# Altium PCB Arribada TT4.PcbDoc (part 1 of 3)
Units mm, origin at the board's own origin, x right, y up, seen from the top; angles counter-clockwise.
Board outline 56 x 35 mm, 6 copper layers (Top Layer, L2GND, L3, L4, L5GND, Bottom Layer), stack 0.865 mm thick; 99 components, 88 nets, 417 pads, 769 vias.
Unrouted connection lines stored in the file: 31.
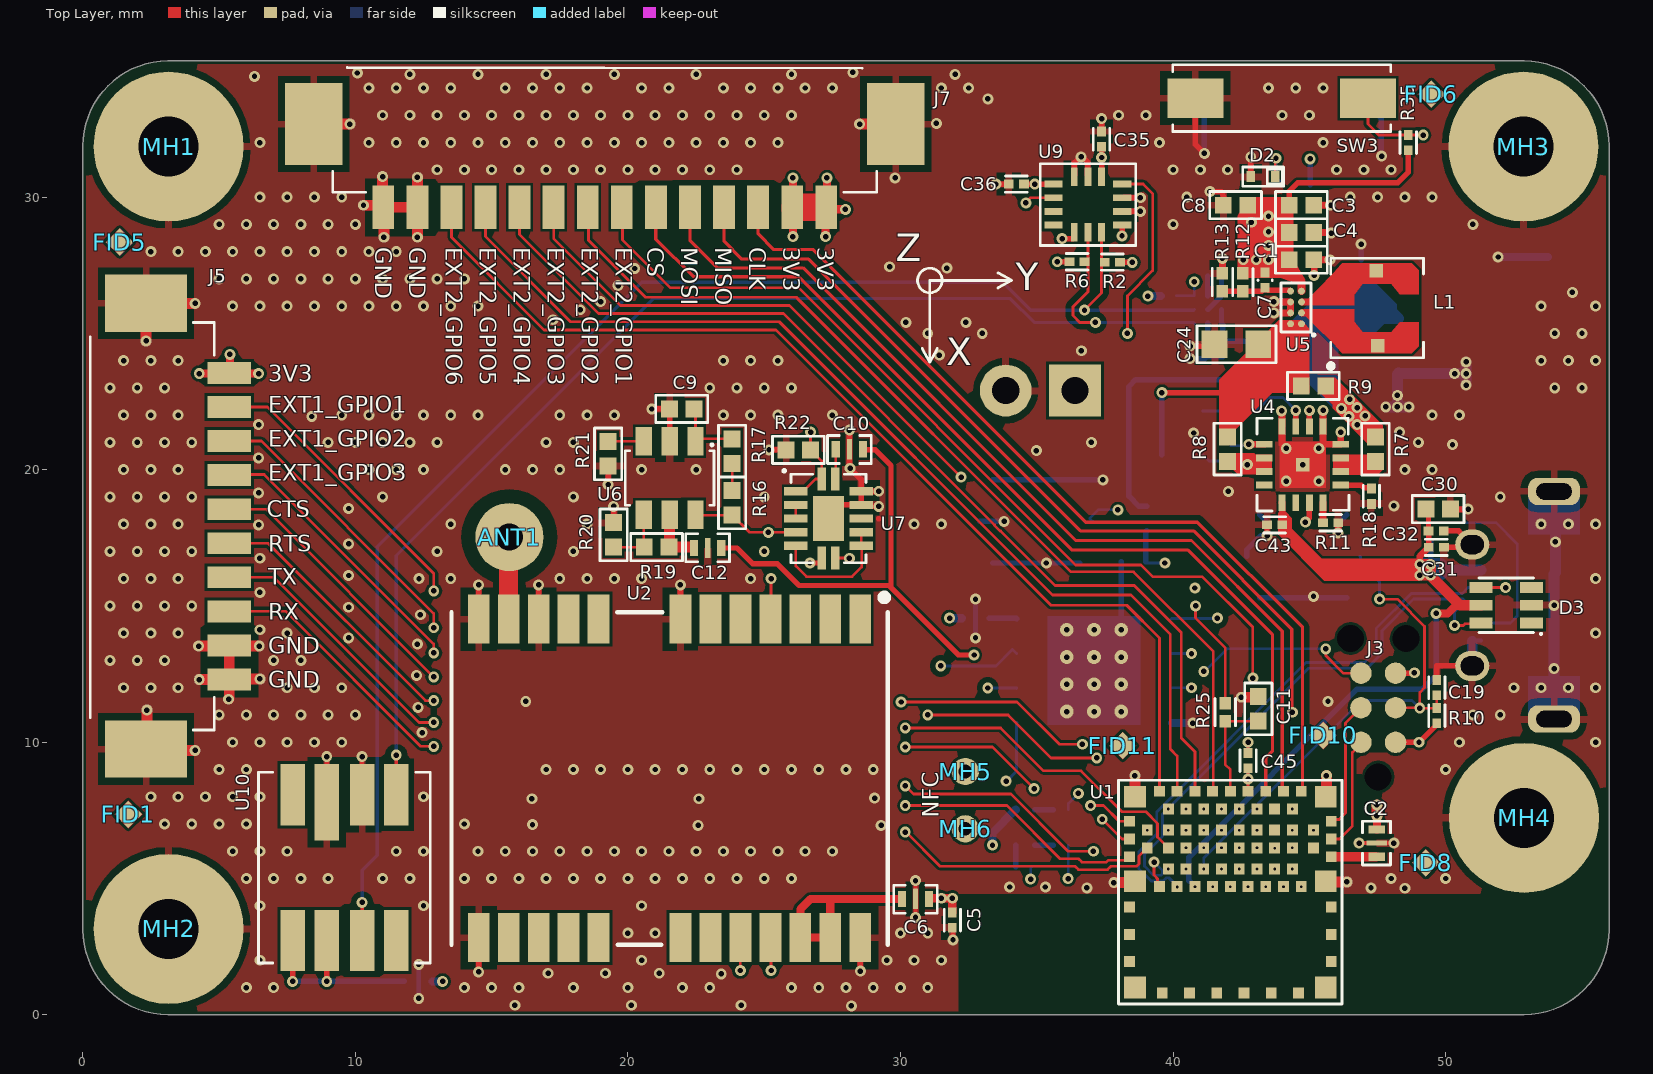
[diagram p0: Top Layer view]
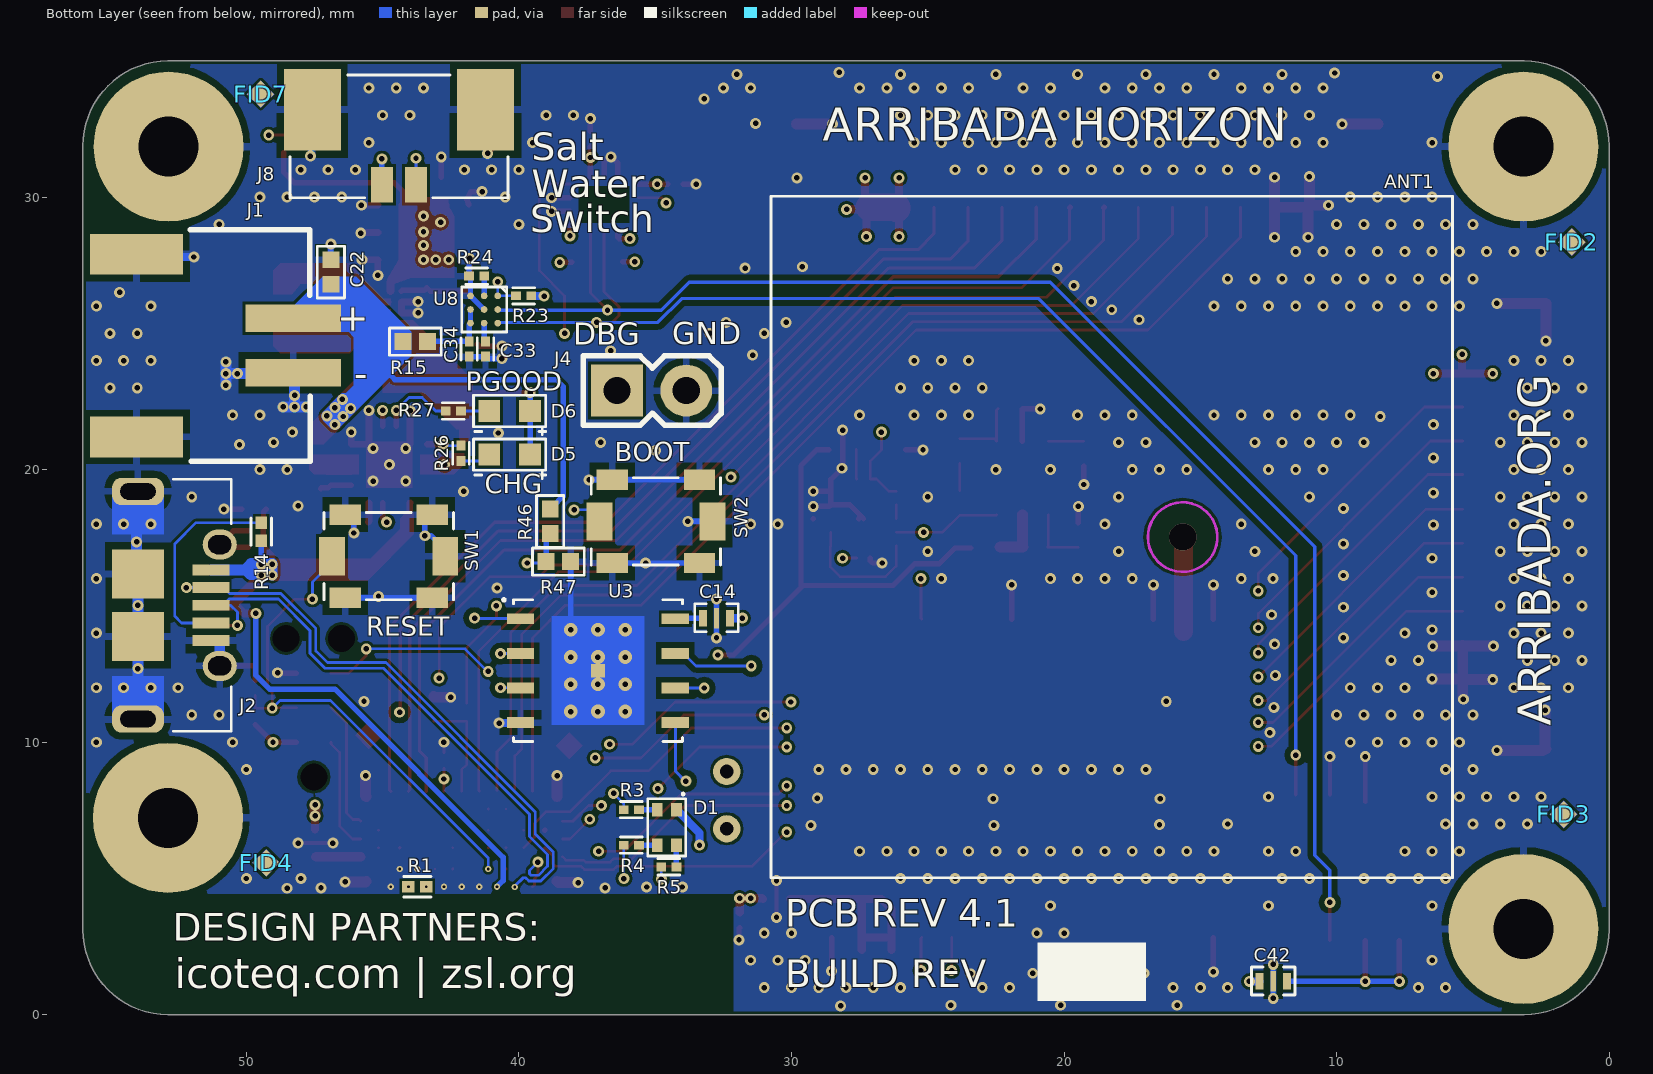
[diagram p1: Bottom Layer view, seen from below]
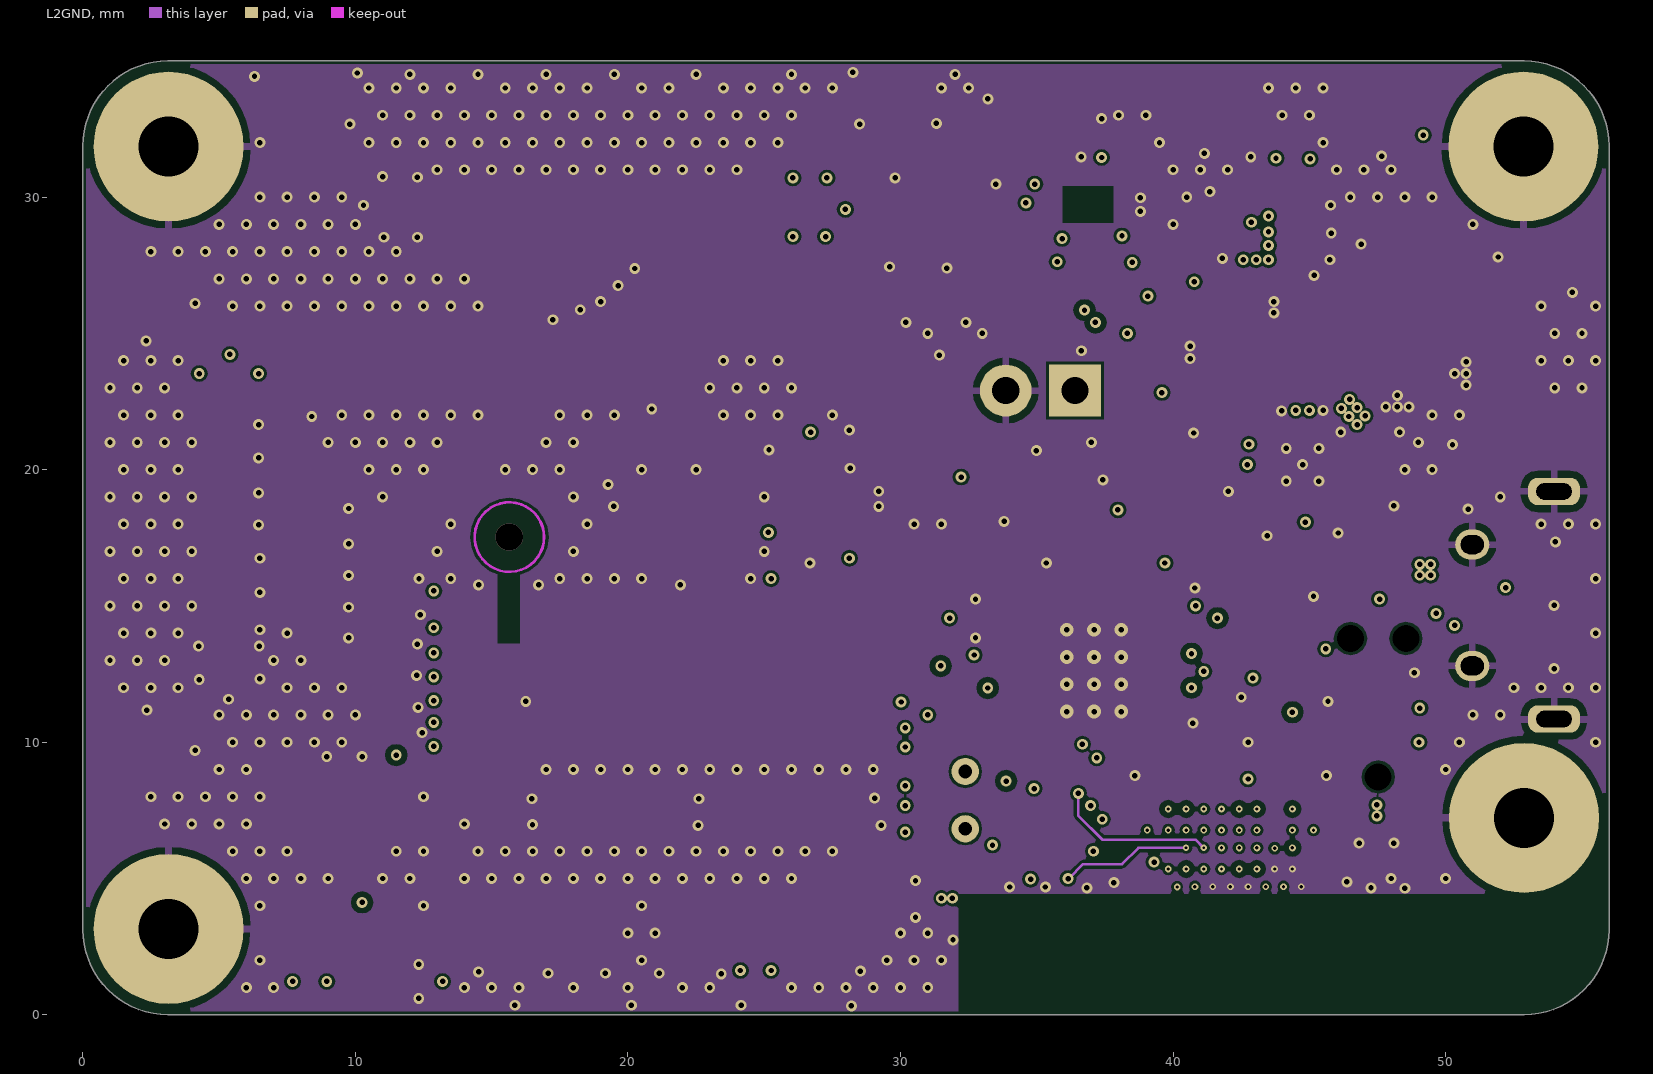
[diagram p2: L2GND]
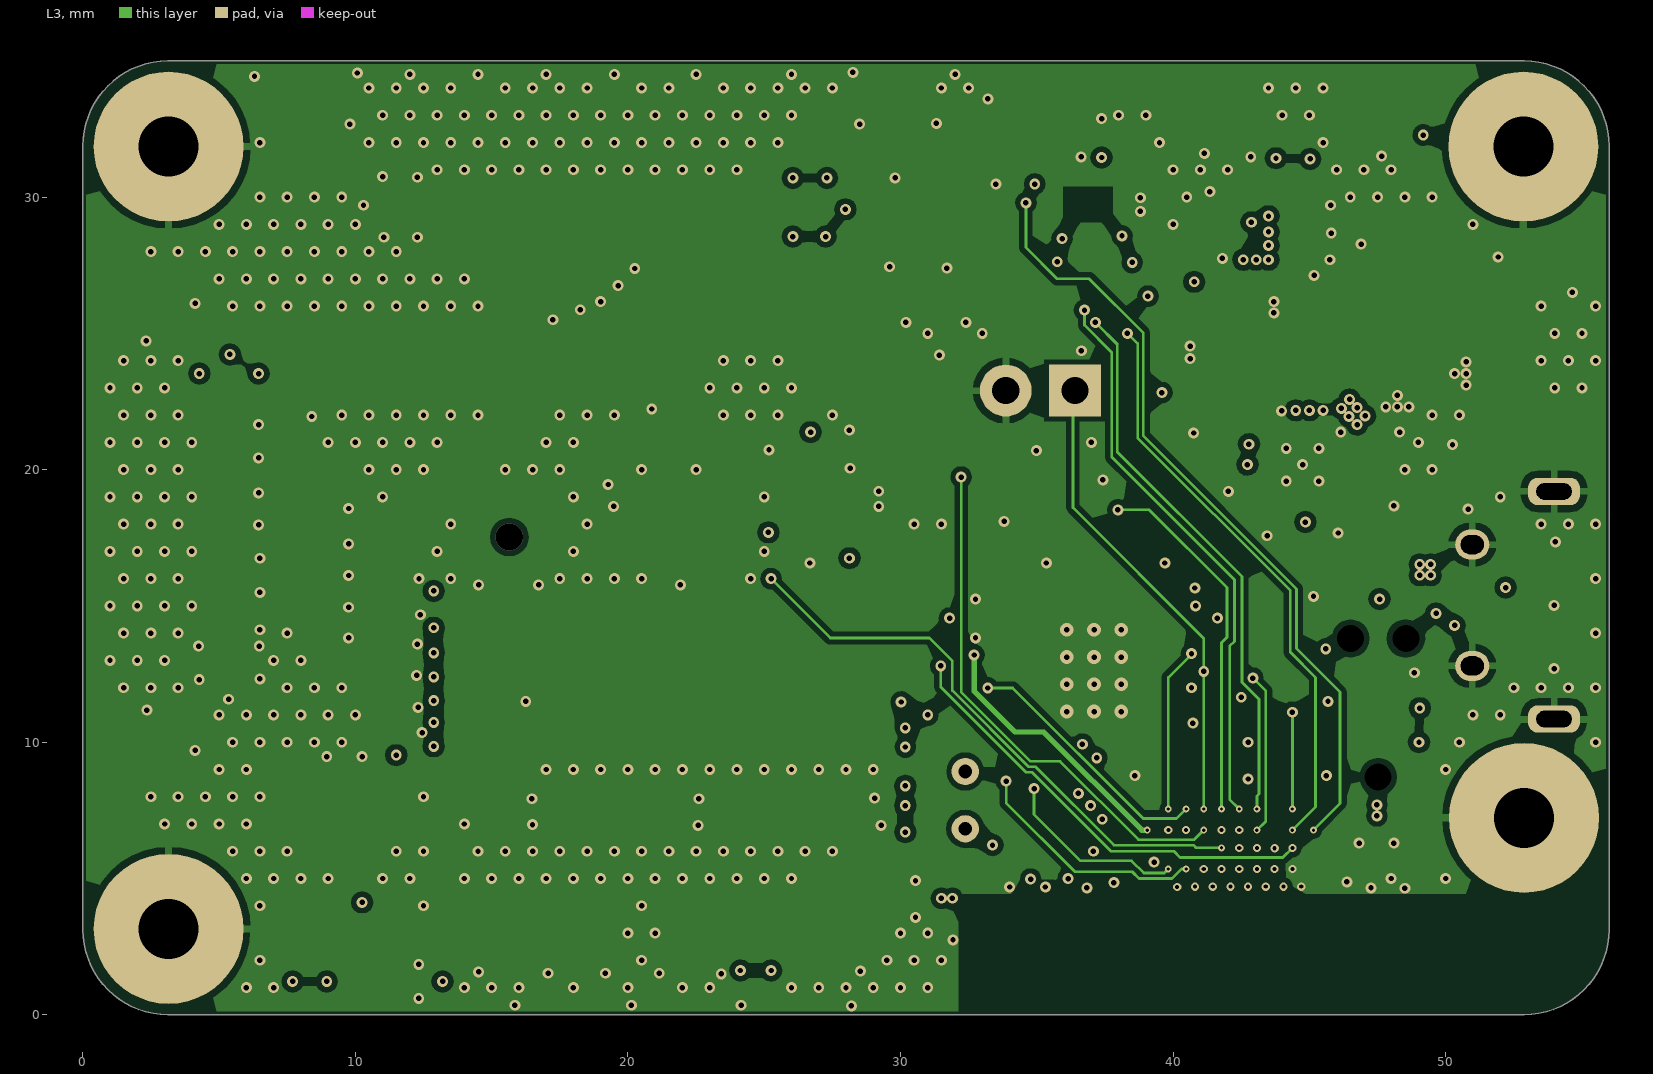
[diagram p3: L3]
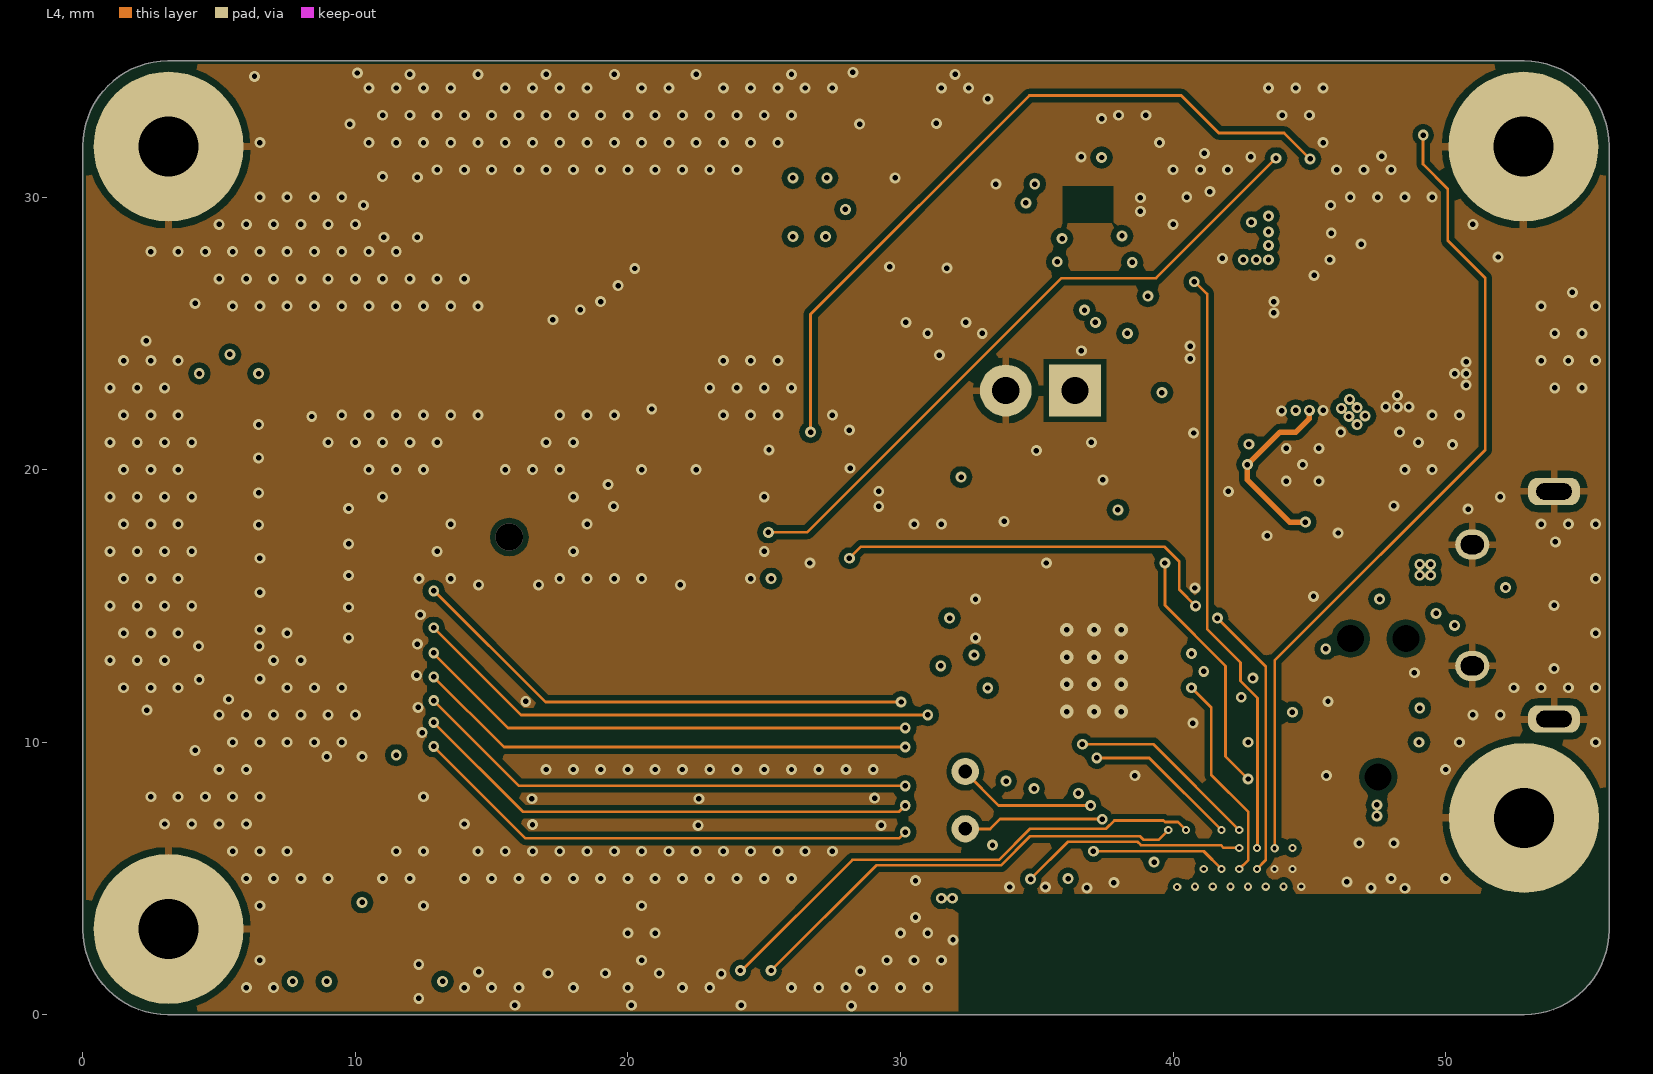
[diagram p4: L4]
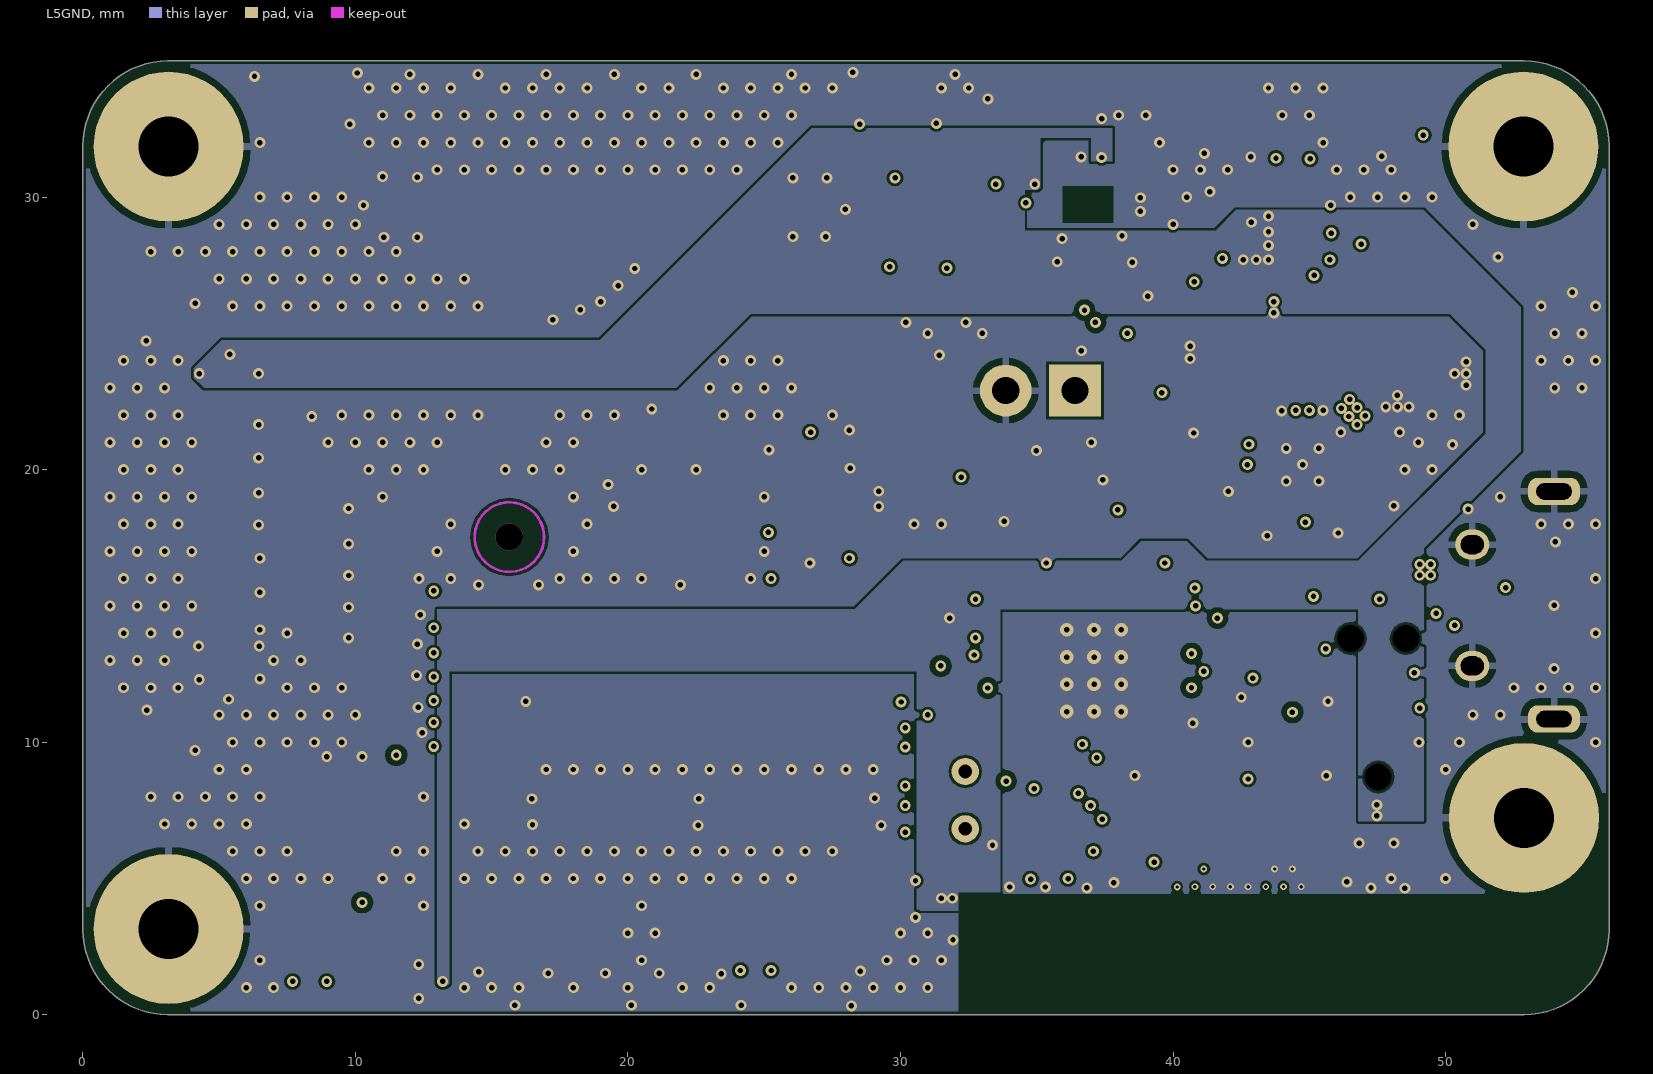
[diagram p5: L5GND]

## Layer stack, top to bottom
Top Solder: solder mask 0.02, Solder Resist, Dk 4.1
Top Layer: signal copper 0.012
Dielectric1: prepreg 0.086, EM-827B-1080_RC68, Dk 3.8
L2GND: signal copper 0.012
Dielectric2: prepreg 0.064, EM-827B-106RC76, Dk 3.7
Dielectric3: core 0.064, EM-827B-106RC76, Dk 3.7
L3: signal copper 0.017
Dielectric4: core 0.355, EM827B, Dk 4.4
L4: signal copper 0.017
Dielectric5: prepreg 0.064, EM-827B-106RC76, Dk 3.7
Dielectric6: dielectric 0.064, EM-827B-106RC76, Dk 3.7
L5GND: signal copper 0.012
Dielectric7: prepreg 0.086, EM-827B-1080_RC68, Dk 3.8
Bottom Layer: signal copper 0.012
Bottom Solder: solder mask 0.02, Solder Resist, Dk 4.1

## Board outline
3.125,0 cw(c3.15,3.15) 0,3.125 0,31.875 cw(c3.15,31.85) 3.125,35 3.15,35 52.875,35 cw(c52.85,31.85) 56,31.875 56,3.125 cw(c52.85,3.15) 52.875,0

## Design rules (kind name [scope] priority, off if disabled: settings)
Clearance "Antenna Pin Top" [InComponent('ANT1')AND OnLayer('Top Layer')] p1: gap=0.5 ignorepadtopadclearanceinfootprint=FALSE
Clearance "50R Clearance" [InNetClass('50R_track') vs InPolygon] p2: gap=0.2 ignorepadtopadclearanceinfootprint=FALSE except(0: Arc-Hole Track-Hole SMDPad-Hole THPad-Hole Via-Hole Fill-Hole Poly-Hole Region-Hole Text-Hole)
Clearance Polygon_named [All vs InNamedPolygon('TOP_GND')or InNamedPolygon('L2GND')or InNamedPolygon('L3_GND')or InNamedPolygon('L4_GND')or InNamedPolygon('L5GND')or InNamedPolygon('BOT_GND')] p3: gap=0.2 ignorepadtopadclearanceinfootprint=FALSE except(0: Arc-Hole Track-Hole SMDPad-Hole THPad-Hole Via-Hole Fill-Hole Poly-Hole Region-Hole Text-Hole)
Clearance [All] p4: gap=0.1 ignorepadtopadclearanceinfootprint=FALSE except(0: Arc-Hole Track-Hole SMDPad-Hole THPad-Hole Via-Hole Fill-Hole Poly-Hole Region-Hole Text-Hole)
Clearance Polygon_general [All vs InPolygon] p5: gap=0.2 ignorepadtopadclearanceinfootprint=FALSE except(0: Arc-Hole Track-Hole SMDPad-Hole THPad-Hole Via-Hole Fill-Hole Poly-Hole Region-Hole Text-Hole)
ComponentClearance [All] p1 off: gap=0.254 collisioncheckmode=3 verticalgap=0.254 showdistances=FALSE
DiffPairsRouting [All] p1: maxlimit=0.108 minlimit=0.102 mostfreqgap=0.108 toplayer_mingap=0.108 toplayer_minwidth=0.1 toplayer_maxwidth=0.102 toplayer_prefwidth=0.102 midlayer1_mingap=0.108 midlayer1_minwidth=0.1 midlayer1_maxwidth=0.102 midlayer1_prefwidth=0.102 midlayer2_maxgap=0.102 midlayer2_prefgap=0.102 midlayer2_minwidth=0.152 midlayer2_maxwidth=0.152 midlayer2_prefwidth=0.152 midlayer3_maxgap=0.102 midlayer3_prefgap=0.102 midlayer3_minwidth=0.152 midlayer3_maxwidth=0.152 midlayer3_prefwidth=0.152 midlayer4_mingap=0.108 midlayer4_minwidth=0.1 midlayer4_maxwidth=0.102 midlayer4_prefwidth=0.102 bottomlayer_mingap=0.108 bottomlayer_minwidth=0.1 bottomlayer_maxwidth=0.102 bottomlayer_prefwidth=0.102 maxuncoupledlength=12.7
FabricationTestPointUsage TestPointUsage [All] p1: valid=0 allowmultiple=FALSE
FabricationTestPointUsage [All] p2: valid=0 allowmultiple=FALSE
FabricationTestpoint Testpoint [All] p1: side=3 testpointundercomponent=TRUE minsize=1.016 maxsize=2.54 preferedsize=1.524 minholesize=0 maxholesize=1.016 preferedholesize=0.813 testpointgrid=0.025 allowsidetop=TRUE allowsidebottom=TRUE usegrid=TRUE gridtolerance=0
FabricationTestpoint [All] p2: side=3 testpointundercomponent=TRUE minsize=1.016 maxsize=2.54 preferedsize=1.524 minholesize=0 maxholesize=1.016 preferedholesize=0.813 testpointgrid=0.025 allowsidetop=TRUE allowsidebottom=TRUE usegrid=TRUE gridtolerance=0
Height [All] p1 off: minheight=0 maxheight=25.4 prefheight=12.7
HoleSize [All] p1: absolutevalues=TRUE maxlimit=6 minlimit=0.015 maxpercent=80.000 minpercent=20.000
HoleSize HoleSize_1 [All] p2: absolutevalues=TRUE maxlimit=2.54 minlimit=0.025 maxpercent=80.000 minpercent=20.000
HoleSize HoleSize_2 [All] p3: absolutevalues=TRUE maxlimit=5 minlimit=0.25 maxpercent=80.000 minpercent=20.000
HoleToHoleClearance [All] p1: gap=0.2 allowstackedmicrovias=TRUE
MinimumAnnularRing [All] p1: minimumring=0.062
MinimumSolderMaskSliver [All] p1 off: minsoldermaskwidth=0.1
PlaneClearance [All] p1: clearance=0.12
PlaneConnect [All] p1: planeconnectstyle=Direct reliefexpansion=0.508 reliefentries=4 reliefconductorwidth=0.254 reliefairgap=0.254
PolygonConnect PolygonConnect_GND [All vs IsNamedPolygon('TJ_GND')] p1: connectstyle=Direct reliefconductorwidth=0.254 reliefentries=4 polygonreliefangle="90 Angle" airgapwidth=0.254
PolygonConnect "PolygonToVia Connect" [IsVia] p2: connectstyle=Direct reliefconductorwidth=0.254 reliefentries=4 polygonreliefangle="90 Angle" airgapwidth=0.254
PolygonConnect PolygonConnect_1 [All] p3: connectstyle=Relief reliefconductorwidth=0.254 reliefentries=4 polygonreliefangle="90 Angle" airgapwidth=0.254
RoutingVias "Thru via" [InDrillLayerPair('Top Layer - Bottom Layer')] p1: holewidth=0.2 width=0.4 viastyle="Through Hole" minholewidth=0.15 minwidth=0.3 maxholewidth=0.2 maxwidth=0.4
RoutingVias TopMicrovia [InDrillLayerPair('Top Layer - L2GND')] p2: holewidth=0.1 width=0.23 viastyle="Through Hole" minholewidth=0.1 minwidth=0.23 maxholewidth=0.15 maxwidth=0.3
RoutingVias BotMicrovia [InDrillLayerPair('L5GND - Bottom Layer')] p3: holewidth=0.1 width=0.23 viastyle="Through Hole" minholewidth=0.1 minwidth=0.23 maxholewidth=0.15 maxwidth=0.3
RoutingVias L2-3Microvia [InDrillLayerPair('L2GND - L3')] p4: holewidth=0.125 width=0.25 viastyle="Through Hole" minholewidth=0.125 minwidth=0.25 maxholewidth=0.2 maxwidth=0.4
RoutingVias L4-5Microvia [InDrillLayerPair('L4 - L5GND')] p5: holewidth=0.125 width=0.25 viastyle="Through Hole" minholewidth=0.125 minwidth=0.25 maxholewidth=0.2 maxwidth=0.4
RoutingVias BuriedviaL3-4 [InDrillLayerPair('L3 - L4')] p6: holewidth=0.15 width=0.3 viastyle="Through Hole" minholewidth=0.15 minwidth=0.3 maxholewidth=0.15 maxwidth=0.3
SilkToSilkClearance [All] p1: silktosilkclearance=0.001
SilkToSolderMaskClearance SilkscreenOverComponentPads [IsPad] p1: minsilkscreentomaskgap=0.001 clearancetoexposedcopper=TRUE
SilkToSolderMaskClearance [IsPad] p2: minsilkscreentomaskgap=0.051 clearancetoexposedcopper=FALSE
SolderMaskExpansion [All] p1: expansion=0.05
Width Width_50R [InNetClass('50R_track')] p1: maxlimit=0.127 minlimit=0.1 preferedwidth=0.102 toplayer_maxwidth=0.121 toplayer_prefwidth=0.121 bottomlayer_maxwidth=0.121 bottomlayer_prefwidth=0.121 minimp=50.000000 maximp=50.000000 favimp=50.000000
Width [All] p2: maxlimit=5 minlimit=0.1 preferedwidth=0.1 minimp=50.000000 maximp=50.000000 favimp=50.000000
18 further rules are at their usual default settings.

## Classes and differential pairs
net class 50R_track: NetANT1_1 NetJ7_3 NetJ7_4 NetJ7_5 NetJ7_6 NetR2_1 NetR6_1 NetU1_11 NetU1_17 NetU1_19 NetU1_45 NetU1_47 NetU1_57 NetU4_C8
component class "Sensors and Interfaces": C9 C10 C11 C12 C35 C36 C42 D2 J3 J4 J5 J7 J8 R16 R17 R19 R20 R21 R22 R25 R35 SW3 U6 U7 U9 U10
component class Power: C1 C3 C4 C7 C8 C22 C24 C30 C31 C32 C33 C34 C43 C? D3 D5 D6 D? FID1 FID2 FID3 FID4 FID5 FID6 FID7 FID8 FID10 FID11 J1 J2 J? L1 L? MH1 MH2 MH3 MH4 Q? R7 R8 R9 R11 R12 R13 R14 R15 R18 R23 R24 R26 R27 R? U4 U5 U8 U?
component class MCU: C2 C14 C19 C45 D1 MH5 MH6 R1 R2 R3 R4 R5 R6 R10 R46 R47 SW1 SW2 U1 U3
component class GNSS: ANT1 C5 C6 U2
differential pair USB_D: +USB_D_P -USB_D_N

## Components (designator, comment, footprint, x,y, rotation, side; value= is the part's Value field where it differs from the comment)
ANT1 "2JCP2540101Ga" 2JCP2540101GA 18.25,17.525 r270 bottom locked
C1 "10UF 0402 6.3V 20% X5R" CAP0402N 44.709,27.7 r180 top value=10uF
C2 "470NF 0402 6.3V +50%/-20%" YFF15PC 47.475,6.3 r270 top value=470nF
C3 "10UF 0402 6.3V 20% X5R" CAP0402N 44.709,29.7 r180 top value=10uF
C4 "10UF 0402 6.3V 20% X5R" CAP0402N 44.709,28.7 r180 top value=10uF
C5 "1UF 0201 10V 20% X5R" CAP0201L 31.9,3.475 r90 top value=1uF
C6 "470NF 0402 6.3V +50%/-20%" YFF15PC 30.55,4.25 r0 top value=470nF
C7 "CAP CER 10PF 0201 25V 5% C0G" Passive0201L 43.375,26.95 r90 top value=10pF
C8 "CAP NF 0402" CAP0402N_NF 42.29,29.7 r0 top value=NF
C9 "10NF 0402 16V 20% X7R" CAP0402N 21.975,22.23 r0 top value=10nF
C10 "470NF 0402 6.3V +50%/-20%" YFF15PC 28.125,20.75 r0 top value=470nF
C11 "1NF 0402 50V 5%" CAP0402N 43.125,11.225 r270 top value=1nF
C12 "470NF 0402 6.3V +50%/-20%" YFF15PC 22.925,17.125 r180 top value=470nF
C14 "470NF 0402 6.3V +50%/-20%" YFF15PC 32.75,14.55 r0 bottom value=470nF
C19 "100NF 0201 35V 10% X5R" CAP0201L 49.675,12 r270 top value=100nF
C22 "4.7UF 0402 10V 20% X5R" CAP0402N 46.9,27.25 r270 bottom value=4.7UF
C24 "10UF 0603 16V 10% X5R" CAP0603N 42.325,24.6 r0 top value=10uF
C30 "4.7UF 0402 10V 20% X5R" CAP0402N 49.725,18.55 r180 top value=4.7UF
C31 "1UF 0201 10V 20% X5R" CAP0201L 49.655,17.15 r180 top value=1uF
C32 "100NF 0201 35V 10% X5R" CAP0201L 49.65,17.75 r180 top value=100nF
C33 "470NF 0201 16V 20% X5R" CAP0201L 41.225,24.425 r90 bottom value=470nF
C34 "1UF 0201 10V 20% X5R" CAP0201L 41.825,24.425 r90 bottom value=1uF
C35 "100NF 0201 35V 10% X5R" CAP0201L 37.375,32.125 r270 top value=100nF
C36 "100NF 0201 35V 10% X5R" CAP0201L 34.25,30.475 r0 top value=100nF
C42 "470NF 0402 6.3V +50%/-20%" YFF15PC 12.325,1.225 r0 bottom value=470nF
C43 "1UF 0201 10V 20% X5R" CAP0201L 43.725,17.975 r0 top value=1uF
C45 "100NF 0201 35V 10% X5R" CAP0201L 42.75,9.325 r270 top value=100nF
D1 "APHF1608LSEEQBDZGKC" "LED RGB 0603" 34.575,6.875 r270 bottom
D2 "ESD9L5.0ST5G" SOD-923 43.3,30.75 r0 top
D3 "RCLAMP0504FBTCT" SC70-6 52.225,15.025 r90 top
D5 "LTST-C190KSKT" DIOD0603N_YELLOW 40.341,20.55 r0 bottom
D6 "LTST-C190KGKT" DIOD0603N_GREEN 40.341,22.15 r0 bottom
FID1 "Fiducial" FIDUCIAL 1.675,7.35 r90 top
FID2 "Fiducial" FIDUCIAL 1.375,28.35 r90 bottom
FID3 "Fiducial" FIDUCIAL 1.675,7.35 r90 bottom
FID4 "Fiducial" FIDUCIAL 49.275,5.575 r90 bottom
FID5 "Fiducial" FIDUCIAL 1.35,28.35 r90 top
FID6 "Fiducial" FIDUCIAL 49.475,33.775 r90 top
FID7 "Fiducial" FIDUCIAL 49.475,33.775 r90 bottom
FID8 "Fiducial" FIDUCIAL 49.275,5.575 r90 top
FID10 "Fiducial" FIDUCIAL 45.5,10.25 r90 top
FID11 "Fiducial" FIDUCIAL 38.15,9.875 r90 top
J1 "S2B-PH-SM4-TB" SM4-2 51.15,24.55 r90 bottom locked
J2 "47589-0001" 0475890001 51.3,15.025 r90 bottom locked
J3 "TC2030-NL" TC2030NL 47.525,8.725 r90 top
J4 "M20-9990245" "HDR 2POS 2.54MM THRU HOLE" 36.4,22.9 r180 bottom
J5 "0532611071" 0532611071 4.425,20.425 r270 top locked
J7 "0532611471" 0532611471 19.15,31.15 r180 top locked
J8 "0533980271" 0533980271 44.4,31.1 r0 bottom locked
L1 "LPS3015-152MRC" "LPS3015 UPDATE" 47.484,25.925 r90 top value=1.5uH
MH1 "Mounting Hole M2 Plated" "MOUNTING HOLE M2 PLATED" 3.15,31.85 r0 top
MH2 "Mounting Hole M2 Plated" "MOUNTING HOLE M2 PLATED" 3.15,3.15 r0 top
MH3 "Mounting Hole M2 Plated" "MOUNTING HOLE M2 PLATED" 52.85,31.85 r0 top
MH4 "Mounting Hole M2 Plated" "MOUNTING HOLE M2 PLATED" 52.875,7.225 r0 top
MH5 "Mounting Hole 0.5mm" "Mounting Hole 0.5mm" 32.375,8.925 r90 top
MH6 "Mounting Hole 0.5mm" "Mounting Hole 0.5mm" 32.375,6.825 r90 top
R1 "0R 0201" RES0201N 43.725,4.7 r0 bottom value=0R
R2 "4.7K 0201 1% 100PPM" RES0201L 37.775,27.61 r0 top value=4.7K
R3 "750R 0201 1% 100PPM" RES0201L 35.875,7.525 r180 bottom value=750R
R4 "330R 0201 1% 100PPM" RES0201L 35.875,6.225 r180 bottom value=330R
R5 "1.6K 0201 1% 100PPM" RES0201L 34.5,5.425 r180 bottom value=1.6K
R6 "4.7K 0201 1% 100PPM" RES0201L 36.475,27.625 r180 top value=4.7K
R7 "0R 0402" RES0402N 47.425,20.75 r90 top value=0R
R8 "0R 0402" RES0402N 42,20.75 r90 top value=0R
R9 "RES NF 0402" RES0402N 45.15,23.075 r0 top value=NF
R10 "10K 0201 1% 100PPM" RES0201L 49.675,10.975 r270 top value=10K
R11 "3.3K 0201 1% 100PPM" RES0201L 45.775,18.05 r180 top value=3.3K
R12 "287K 0201 1% 100PPM" RES0201N 42.559,26.875 r90 top value=287K
R13 "51.1K 0201 1% 100PPM" RES0201N 41.809,26.875 r270 top value=51.1K
R14 "100K 0201 1% 100PPM" RES0201N 49.45,17.725 r270 bottom value=100K
R15 "0R 0402" RES0402N 43.8,24.7 r0 bottom value=0R
R16 "10K 0402 1%" RES0402N 23.825,18.78 r90 top value=10K
R17 "10K 0402 1%" RES0402N 23.825,20.68 r90 top value=10K
R18 "10K 0201 1% 100PPM" RES0201L 47.275,19.025 r90 top value=10K
R19 "1M 0402 1%" RES0402N 21.05,17.155 r0 top value=1M
R20 "280K 0402 1% 100PPM" RES0402N 19.475,17.605 r270 top value=280K
R21 "100K 0402 1%" RES0402N 19.275,20.58 r90 top value=100K
R22 "1M 0402 1%" RES0402N 26.25,20.725 r0 top value=1M
R23 "10K 0201 1% 100PPM" RES0201L 39.825,26.375 r180 bottom value=10K
R24 "10K 0201 1% 100PPM" RES0201L 41.55,27.1 r180 bottom value=10K
R25 "330R 0201 1% 100PPM" RES0201N 41.91,11.1 r270 top value=330R
R26 "620R 0201 1% 200PPM" RES0201L 42.125,20.6 r270 bottom value=620R
R27 "330R 0201 1% 100PPM" RES0201L 42.4,22.15 r180 bottom value=330R
R35 "10K 0201 1% 100PPM" RES0201L 48.625,32 r270 top value=10K
R46 "680K 0402 1%" RES0402N 38.85,18.1 r90 bottom value=680K
R47 "1M 0402 1%" RES0402N 38.55,16.625 r0 bottom value=1M
SW1 "PTS820J2x" TL1015 44.775,16.825 r0 bottom
SW2 "PTS820J2x" TL1015 34.975,18.1 r0 bottom
SW3 "SW REED SPST" CT05 43.982,33.627 r0 top
U1 "ISP1807-LR" ISP1807-LR 42.1,4.5 r0 top locked
U2 "NEO-M8N" NEO 21.525,8.675 r270 top locked
U3 "IS25LP128F-JKLE" SON127P600X80_HS-9N 37.1,12.625 r180 bottom
U4 "BQ24230RGT" VQFN-16 44.75,20.182 r180 top
U5 "TPS63036YFGR" BGA8C40P2X4_108X181X62 44.509,25.95 r180 top
U6 "LTC6995IS6" SOT-23_DBV 21.53,19.695 r270 top
U7 "74HC132BQ-Q100X" DHVQFN14 27.359,18.205 r0 top
U8 "BQ27621YZFR-G1A" DSBGA-9 41.275,25.875 r270 bottom
U9 "BMX160" LGA14 36.875,29.725 r180 top
U10 "MS5803-14BA" MS5803 9.6,5.4 r270 top locked

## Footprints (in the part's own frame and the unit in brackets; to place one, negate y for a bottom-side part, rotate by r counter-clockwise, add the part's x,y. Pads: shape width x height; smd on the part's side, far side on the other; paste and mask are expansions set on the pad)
2JCP2540101GA [mm] "GNSS PATCH ANTENNA"
  round 2.5 smd far side: 1(0,2.6)
  silkscreen extent -12.5,-12.5 12.5,12.5, body extent -12.5,-12.5 12.5,12.5, height 4.91
0475890001 [mm] "Micro USB AB"
  rect 0.4x1.35 smd: 1(1.3,0) 2(0.65,0) 3(0,0) 4(-0.65,0) 5(-1.3,0)
  oval 1.1x1.25 hole 0.7 slot 0.85 at 90 deg: G1(-2.225,-0.325) G2(2.225,-0.325)
  rrect70% 1x1.9 hole 0.6 slot 1.3 at 90 deg: G3(-4.175,2.675) G4(4.175,2.675)
  rect 1.8x1.9 smd: G5(-1.15,2.675) G6(1.15,2.675)
  Top Layer region: -2.6,3.625 -2.6,1.725 -4.025,1.725 -3.875,1.875 -3.75,1.875 -3.75,3.375 -4,3.625
  Top Layer region: 2.6,3.625 2.6,1.725 4.025,1.725 3.875,1.875 3.75,1.875 3.75,3.375 4,3.625
  silkscreen extent -4.62,-0.75 4.62,1.38, body extent -4.35,-0.5 4.3,5.39, height 2.72
0532611071 [mm]
  rect 0.8x1.6 smd: 1(-3.125,0.95) 2(-1.875,0.95) 3(-0.625,0.95) 4(0.625,0.95) 5(1.875,0.95) 6(3.125,0.95) 7(4.375,0.95) 8(5.625,0.95) 9(6.875,0.95) 10(8.125,0.95)
  rect 2.1x3 smd: 11(-5.675,-2.1) 12(10.675,-2.1)
  silkscreen extent -4.97,-4.15 9.97,0.4, body extent -6.33,-4 11.32,1.2, height 3.41
0532611471 [mm]
  rect 0.8x1.6 smd: 1(-8.125,1.525) 2(-6.875,1.525) 3(-5.625,1.525) 4(-4.375,1.525) 5(-3.125,1.525) 6(-1.875,1.525) 7(-0.625,1.525) 8(0.625,1.525) 9(1.875,1.525) 10(3.125,1.525) 11(4.375,1.525) 12(5.625,1.525) 13(6.875,1.525) 14(8.125,1.525)
  rect 2.1x3 smd: 15(10.675,-1.525) 16(-10.675,-1.525)
  silkscreen extent -9.97,-3.6 9.97,0.97, body extent -11.32,-3.43 11.32,1.78, height 3.41
0533980271 [mm]
  rect 0.8x1.3 smd: 1(-0.625,0.65) 2(0.625,0.65)
  rect 2.1x3 smd: 3(-3.175,-2.1) 4(3.175,-2.1)
  silkscreen extent -4,-3.37 4,1.12, body extent -3.82,-3.2 3.83,1, height 4.71
BGA8C40P2X4_108X181X62 [mm] "BGA, 8-Leads, Body 1.08x1.81mmx0.63mm, Pitch 0.40mm"
  round 0.25 smd: A1(-0.2,0.6) A2(0.2,0.6) B1(-0.2,0.2) B2(0.2,0.2) C1(-0.2,-0.2) C2(0.2,-0.2) D1(-0.2,-0.6) D2(0.2,-0.6)
  silkscreen extent -0.69,-0.9 0.55,1.06, body extent -0.54,-0.91 0.54,0.9, height 0.63
CAP0201L [mm]
  rect 0.36x0.32 smd: 1(-0.28,0) 2(0.28,0)
  silkscreen extent -0.4,-0.3 0.4,0.3, body extent -0.31,-0.16 0.31,0.16, height 0.3
CAP0402N [mm]
  rect 0.62x0.62 smd: 1(-0.45,0) 2(0.45,0)
  silkscreen extent -0.95,-0.5 0.95,0.5, body extent -0.52,-0.27 0.53,0.28, height 0.4
CAP0402N_NF [mm]
  rect 0.62x0.62 smd: 1(-0.45,0) 2(0.45,0)
  silkscreen extent -0.95,-0.5 0.95,0.5
CAP0603N [mm]
  rect 0.95x1 smd: 1(-0.8,0) 2(0.8,0)
  silkscreen extent -1.45,-0.67 1.45,0.67, body extent -0.85,-0.47 0.85,0.47, height 0.6
CT05 [mm] "Dry reed switch J-lead"
  rect 2.06x1.45 smd: 1(-3.165,0) 2(3.165,0)
  silkscreen extent -4,-1.23 4,1.23, body extent -3.78,-1.16 3.78,1.16, height 2.39
DHVQFN14 [mm] "74HC132BQ-Q100X"
  rect 0.3x0.85 smd: 1(-0.25,1.45) 7(-0.25,-1.45) 8(0.25,-1.45) 14(0.25,1.45)
  rect 0.85x0.3 smd: 2(-1.2,1) 3(-1.2,0.5) 4(-1.2,0) 5(-1.2,-0.5) 6(-1.2,-1) 9(1.2,-1) 10(1.2,-0.5) 11(1.2,0) 12(1.2,0.5) 13(1.2,1)
  rect 1.15x1.65 smd: 15(0,0)
  silkscreen extent -1.67,-1.63 1.38,1.8, body extent -1.3,-1.55 1.3,1.55, height 1
DIOD0603N_GREEN [mm] "DIODE 0603N"
  rect 0.8x0.8 smd: 1(-0.75,0) 2(0.75,0)
  silkscreen extent -1.33,-0.58 1.33,0.87, body extent -0.81,-0.4 0.81,0.4, height 0.6
DIOD0603N_YELLOW [mm] "DIODE 0603N"
  rect 0.8x0.8 smd: 1(-0.75,0) 2(0.75,0)
  silkscreen extent -1.33,-0.58 1.33,0.87, body extent -0.81,-0.4 0.81,0.4, height 1.11
DSBGA-9 [mm] "9 ball BGA 0.5mm pitch"
  round 0.245 smd: A1(-0.5,0.5) A2(0,0.5) A3(0.5,0.5) B1(-0.5,0) B2(0,0) B3(0.5,0) C1(-0.5,-0.5) C2(0,-0.5) C3(0.5,-0.5)
  silkscreen extent -0.82,-0.82 0.82,0.82, body extent -0.82,-0.82 0.82,0.82, height 27.4
FIDUCIAL [mm]
  rect 0.707x0.707 smd rot 45: 1(0,0)
  Top Layer region: -0.5,0 0,0.5 0.5,0 0,-0.5
"HDR 2POS 2.54MM THRU HOLE" [mm]
  rect 1.9x1.9 hole 1: 1(0,0)
  round 1.9 hole 1: 2(2.54,0)
  silkscreen extent -1.24,-1.28 3.83,1.28, body extent -1.25,-1.27 3.83,1.27, height 8.65
ISP1807-LR [mm] "Insight SiP BLE module all pins"
  rect 0.8x0.8 smd mask+0.05: 1(-3.5,3.5) 7(-3.5,0.4) 25(3.5,0.4) 31(3.5,3.5) 68(-3.5,-3.5) 75(3.5,-3.5)
  rect 0.4x0.4 smd mask+0.05: 2(-3.7,2.6) 3(-3.05,2.275) 4(-3.7,1.95) 5(-3.05,1.625) 6(-3.7,1.3) 8(-2.6,0.2) 9(-2.275,0.85) 10(-1.95,0.2) 11(-1.625,0.85) 12(-1.3,0.2) 13(-0.975,0.85) 14(-0.65,0.2) 15(-0.325,0.85) 16(0,0.2) 17(0.325,0.85) 18(0.65,0.2) 19(0.975,0.85) 20(1.3,0.2) 21(1.625,0.85) 22(1.95,0.2) 23(2.275,0.85) 24(2.6,0.2) 26(3.7,1.3) 27(3.05,1.625) 28(3.7,1.95) 29(3.05,2.275) 30(3.7,2.6) 32(2.6,3.7) 33(2.275,3.05) 34(1.95,3.7) 35(1.625,3.05) 36(1.3,3.7) 37(0.975,3.05) 38(0.65,3.7) 39(0.325,3.05) 40(0,3.7) 41(-0.325,3.05) 42(-0.65,3.7) 43(-0.975,3.05) 44(-1.3,3.7) 45(-1.625,3.05) 46(-1.95,3.7) 47(-2.275,3.05) 48(-2.6,3.7) 49(2.275,2.275) 50(1.625,2.275) 51(0.975,2.275) 52(0.325,2.275) 53(-0.325,2.275) 54(-0.975,2.275) 55(-1.625,2.275) 56(-2.275,2.275) 57(2.275,1.625) 58(1.625,1.625) 59(0.975,1.625) 60(0.325,1.625) 61(-0.325,1.625) 62(-0.975,1.625) 63(-1.625,1.625) 64(-2.275,1.625) 65(-3.7,-0.55) 66(-3.7,-1.55) 67(-3.7,-2.55) 69(-2.5,-3.7) 70(-1.5,-3.7) 71(-0.5,-3.7) 72(0.5,-3.7) 73(1.5,-3.7) 74(2.5,-3.7) 76(3.7,-2.55) 77(3.7,-1.55) 78(3.7,-0.55)
  silkscreen extent -4.1,-4.1 4.1,4.1, body extent -4,-4 4,4.01, height 1.2
"LED RGB 0603" [mm]
  rect 0.5x0.4 smd: 1(-0.65,0.35) 2(-0.65,-0.35) 3(0.65,-0.35) 4(0.65,0.35)
  silkscreen extent -1.26,-0.7 1.05,0.7, body extent -0.8,-0.4 0.8,0.4, height 0.51
LGA14 [mm]
  rect 0.675x0.25 smd: 1(-1.262,0.75) 2(-1.262,0.25) 3(-1.262,-0.25) 4(-1.262,-0.75) 8(1.262,-0.75) 9(1.262,-0.25) 10(1.262,0.25) 11(1.262,0.75)
  rect 0.25x0.675 smd: 5(-0.5,-1.012) 6(0,-1.012) 7(0.5,-1.012) 12(0.5,1.012) 13(0,1.012) 14(-0.5,1.012)
  round 0.2 on Top Overlay: ""(-1.575,1.325)
  silkscreen extent -1.75,-1.5 1.75,1.5, body extent -1.5,-1.25 1.5,1.25, height 1
"LPS3015 UPDATE" [mm] "LPS3015"
  rect 0.5x0.5 smd: 1(-1.375,-0.025) 2(1.375,0.025)
  Top Layer region: 0.51,-1.525 1.395,-1.525 1.65,-1.27 1.65,1.27 1.395,1.525 0.51,1.525 0.51,0.825 0.89,0.525 0.89,-0.525 0.51,-0.825
  Top Layer region: -0.51,-1.525 -1.395,-1.525 -1.65,-1.27 -1.65,1.27 -1.395,1.525 -0.51,1.525 -0.51,0.825 -0.89,0.525 -0.89,-0.525 -0.51,-0.825
  silkscreen extent -2.17,-1.7 1.83,1.75, body extent -1.58,-1.58 1.58,1.58, height 1.51
"Mounting Hole 0.5mm" [mm]
  round 1 hole 0.5: 1(0,0)
"MOUNTING HOLE M2 PLATED" [mm]
  round 5.5 hole 2.2: 1(0,0)
MS5803 [mm] "Pressure sensor"
  rect 2.25x0.9 smd: 1(-2.675,1.9) 2(-2.675,0.65) 4(-2.675,-1.9) 5(2.675,-1.9) 6(2.675,-0.65) 7(2.675,0.65) 8(2.675,1.9)
  rect 2.8x0.9 smd: 3(-2.4,-0.65)
  round 0.2 on Top Overlay: ""(-3.725,2.9)
  silkscreen extent -3.5,-3.15 3.5,3.15, body extent -3.2,-3.1 3.2,3.1, height 3.08
NEO [mm] "u-blox NEO GNSS module"
  rect 1.8x0.8 smd paste-0.1: 1(-5.842,7) 2(-5.842,5.9) 3(-5.842,4.8) 4(-5.842,3.7) 5(-5.842,2.6) 6(-5.842,1.5) 7(-5.842,0.4) 8(-5.842,-2.6) 9(-5.842,-3.7) 10(-5.842,-4.8) 11(-5.842,-5.9) 12(-5.842,-7) 13(5.842,-7) 14(5.842,-5.9) 15(5.842,-4.8) 16(5.842,-3.7) 17(5.842,-2.6) 18(5.842,0.4) 19(5.842,1.5) 20(5.842,2.6) 21(5.842,3.7) 22(5.842,4.8) 23(5.842,5.9) 24(5.842,7)
  silkscreen extent -6.69,-8 6.11,8, body extent -6.1,-8 6.1,8, height 2.28
Passive0201L [mm] "Generic 0201L size to IPC"
  rect 0.36x0.32 smd: 1(-0.28,0) 2(0.28,0)
  silkscreen extent -0.01,-0.26 0.01,0.26, body extent -0.31,-0.16 0.31,0.16, height 0.3
RES0201L [mm]
  rect 0.36x0.32 smd: 1(-0.28,0) 2(0.28,0)
  silkscreen extent -0.4,-0.3 0.4,0.3, body extent -0.31,-0.16 0.31,0.16, height 0.3
RES0201N [mm]
  rect 0.46x0.42 smd: 1(-0.33,0) 2(0.33,0)
  silkscreen extent -0.5,-0.38 0.5,0.38, body extent -0.31,-0.16 0.31,0.16, height 0.3
RES0402N [mm]
  rect 0.62x0.62 smd: 1(-0.45,0) 2(0.45,0)
  silkscreen extent -0.95,-0.5 0.95,0.5, body extent -0.52,-0.27 0.53,0.28, height 0.4
SC70-6 [mm]
  rect 0.4x0.85 smd: 1(-0.65,-0.925) 2(0,-0.925) 3(0.65,-0.925) 4(0.65,0.925) 5(0,0.925) 6(-0.65,0.925)
  silkscreen extent -1.07,-1.3 1,1, body extent -1,-1.05 1,1.05, height 0.96
SM4-2 [mm] "S2B-PH-SM4-TB"
  rect 1x3.5 smd: 1(1,-2.875) 2(-1,-2.875)
  rect 1.5x3.4 smd: 3(-3.35,2.875) 4(3.35,2.875)
  silkscreen extent -4.25,-3.5 4.25,0.9, body extent -3.95,-4.27 3.95,4.33, height 5.61
SOD-923 [mm]
  rect 0.3x0.4 smd: 1(-0.45,0) 2(0.45,0)
  silkscreen extent -0.75,-0.35 0.75,0.35, body extent -0.5,-0.3 0.5,0.3, height 0.41
SON127P600X80_HS-9N [mm] "SON, 8-Leads, Body 5.00x6.00mm, Pitch 1.27mm, Thermal Pad 4.00x3.40mm, IPC Medium Density"
  rect 1x0.4 smd: 1(-2.84,1.905) 2(-2.84,0.635) 3(-2.84,-0.635) 4(-2.84,-1.905) 5(2.84,-1.905) 6(2.84,-0.635) 7(2.84,0.635) 8(2.84,1.905)
  rect 0.5x0.5 smd paste-1.7: 9(0,0)
  Top Layer region: -1.7,2 1.7,2 1.7,-2 -1.7,-2
  silkscreen extent -3.5,-2.6 3.1,2.65, body extent -3,-2.5 3,2.5, height 0.8
SOT-23_DBV [mm] "SOT-23 DBV"
  rect 1.05x0.6 smd: 1(-1.35,0.95) 2(-1.35,0) 3(-1.35,-0.95) 4(1.35,-0.95) 5(1.35,0) 6(1.35,0.95)
  silkscreen extent -1.25,-1.63 1,1.63, body extent -1.42,-1.46 1.42,1.46, height 1.1
TC2030NL [mm]
  round 0.787 smd paste-0.787: 1(1.27,-0.635) 2(1.27,0.635) 3(2.54,-0.635) 4(2.54,0.635) 5(3.81,-0.635) 6(3.81,0.635)
  round 0.65 hole 0.991 unplated: H1(0,0) H2(5.08,1.016) H3(5.08,-1.016)
TL1015 [mm] "SM Push Button Switch"
  rect 0.95x1.4 smd: 1(-2.075,0) 2(2.075,0)
  rect 1.15x0.75 smd: G1(-1.6,1.525) G2(1.6,1.525) G3(1.6,-1.525) G4(-1.6,-1.525)
  silkscreen extent -2.37,-1.6 2.37,1.6, body extent -2.3,-1.5 2.3,1.5, height 2
VQFN-16 [mm]
  rect 0.6x0.25 smd: 1(-1.4,0.75) 2(-1.4,0.25) 3(-1.4,-0.25) 4(-1.4,-0.75) 9(1.4,-0.75) 10(1.4,-0.25) 11(1.4,0.25) 12(1.4,0.75)
  rect 0.25x0.6 smd: 5(-0.75,-1.4) 6(-0.25,-1.4) 7(0.25,-1.4) 8(0.75,-1.4) 13(0.75,1.4) 14(0.25,1.4) 15(-0.25,1.4) 16(-0.75,1.4)
  rect 0.5x0.5 smd paste-0.5 mask+0.102: 17(0,0)
  round 0.3 on Top Overlay: ""(-2.025,1.375)
  Top Layer region: -0.85,-0.85 0.85,-0.85 0.85,0.85 -0.85,0.85
  silkscreen extent -1.7,-1.7 1.68,1.7, body extent -1.55,-1.55 1.55,1.55, height 1
YFF15PC [mm] "TDK feedthrough capacitor"
  rect 0.3x0.6 smd: 1(-0.5,0) 2(0.5,0)
  rect 0.19x0.75 smd paste-0.19 mask-0.19: 3(0,0)
  silkscreen extent -0.8,-0.53 0.8,0.5, body extent -0.5,-0.3 0.5,0.3, height 0.31

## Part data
ANT1: "GNSS ANTENNA CERAMIC PATCH GPS/GALILEO/GLONASS/BEIDOU", Manufacturer="2J ANTENNAS", Manufacturers Part Number="2JCP2540106Ca (2J66)"
C1 C3 C4: library part "CAP CER 10UF 0402 6.3V 20% X5R", "CAP CER 10UF 0402 6.3V 20% X5R", Dielectric=X5R, Manufacturer="Taiyo Yuden", Manufacturers Part Number=JMK105CBJ106MV-F, Supplier Part Number 1=963-JMK105CBJ106MV-F, Tolerance=20%, Voltage=6.3V
C2 C6 C10 C12 C14 C42: library part "CAP FEEDTHRU 470NF 0402 6.3V +50%/-20%", "CAP FEEDTHRU 470NF 0402 6.3V +50%/-20%", Manufacturer=TDK, Manufacturers Part Number=YFF15PC0J474M, Supplier Part Number 1=810-CKD710JB0J474S, Tolerance=+50%/-20%, Voltage=6.3V
C5 C31 C34 C43: library part "CAP CER 1UF 0201 10V 20% X5R", "CAP CER 1UF 0201 10V 20% X5R", Dielectric=X5R, Manufacturer=Murata, Manufacturers Part Number=GRM033R61A105ME15D, Supplier Part Number 1=81-GRM033R61A105ME5D, Tolerance=20%, Voltage=10V
C7: Dielectric=C0G, Manufacturer=Murata, Manufacturers Part Number=GRM0335C1E100JA01D, Supplier Part Number 1=81-GRM0335C1E100JA1D, Tolerance=5%, Voltage=25V
C8 FID1 FID2 FID3 FID4 FID5 FID6 FID7 FID8 FID10 FID11 MH1 MH2 MH3 MH4 MH5 MH6 R9: Manufacturer="NOT FITTED PART"
C9: library part "CAP CER 10NF 0402 16V 20% X7R", "CAP CER 10NF 0402 16V 20% X7R", Dielectric=X7R, Manufacturer=AVX, Manufacturers Part Number=0402YC103MAT2A, Supplier Part Number 1=581-0402YC103MAT2A, Tolerance=20%, Voltage=16V
C11: library part "CAP CER 1NF 0402 50V 5% C0G", "CAP CER 1NF 0402 50V 5% C0G", Dielectric=C0G, Manufacturer=Murata, Manufacturers Part Number=GRM1555C1H102JA01D, Supplier Part Number 1=81-GRM1555C1H102JA1D, Tolerance=5%, Voltage=50V
C19 C32 C35 C36 C45: library part "CAP CER 100NF 0201 35V 10% X5R", "CAP CER 100NF 0201 35V 10% X5R", Dielectric=X5R, Manufacturer=Murata, Manufacturers Part Number=GRM033R6YA104KE14D, Supplier Part Number 1=81-GRM33R6YA104KE14D, Tolerance=10%
C22 C30: library part "CAP CER 4.7UF 0402 10V 20% X5R", "CAP CER 4.7UF 0402 10V 20% X5R", Dielectric=X5R, Manufacturer=TDK, Manufacturers Part Number=C1005X5R1A475M050BC, Supplier Part Number 1=810-C1005X5R1A475M, Tolerance=20%, Voltage=10V
C24: library part "CAP CER 10UF 0603 16V 10% X5R", "CAP CER 10UF 0603 16V 10% X5R", Dielectric=X5R, Manufacturer=Murata, Manufacturers Part Number=GRT188R61C106KE13D, Supplier Part Number 1=81-GRT188R61C106KE3D, Tolerance=10%, Voltage=16V
C33: library part "CAP CER 470NF 0201 16V 20% X5R", "CAP CER 470NF 0201 16V 20% X5R", Dielectric=X5R, Manufacturer="Taiyo Yuden", Manufacturers Part Number=EMK063BBJ474MPLF, Supplier Part Number 1=963-EMK063BBJ474MPLF, Tolerance=20%, Voltage=16V
D1: library part "LED RGB 0603 2MA", "LED RGB 0603 2MA", Colour=RGB, Manufacturer=Kingbright, Supplier Part Number 1=604-APHF1608LQBDZGKC
D2: "DIO TVS 5.4V 1A SOD-923", Manufacturer="ON Semiconductor", Supplier Part Number 1=863-ESD9L5.0ST5G, Zener Voltage=5.4V
D3: "DIO ARRAY ESD", Manufacturer=Semtech, Supplier Part Number 1=RCLAMP0504FBTCTCT-ND
D5: library part "LED YELLOW 0603 20MA VF=2V", "LED YELLOW 0603 20MA VF=2V", Colour=Yellow, Manufacturer="Lite-On Inc", Supplier Part Number 1=859-LTST-C190KSKT
D6: library part "LED GREEN 0603 20MA VF=2V", "LED GREEN 0603 20MA VF=2V", Colour=Green, Manufacturer="Lite-On Inc", Supplier Part Number 1=859-LTST-C190KGKT
J1: library part "CON HDR 2POS 2.0MM PITCH", "CON HDR 2POS 2.0MM PITCH", Frequency Range=DC, Manufacturer="JST Sales America", Manufacturers Part Number=S2B-PH-SM4-TB(LF)(SN), Supplier Part Number 1=455-1749-1-ND
J2: library part "CON MICRO USB 2.0 TYPE AB R/A SMD", "CON MICRO USB 2.0 TYPE AB R/A SMD", Manufacturer=Molex, Supplier Part Number 1=WM17143CT-ND
J3: "CON PLUG OF NAILS 6 PIN FOOTPRINT NO LEGS", Manufacturer=Tag-Connect, Manufacturers Part Number="NOT FITTED PART"
J4: "CON HDR 2POS HEADER 2.54MM VERT THRU HOLE", Manufacturer=Harwin, Supplier Part Number 1=952-2261-ND
J5: "CON PICOBLADE 10POS HEADER 1.25MM HORIZ SMD", ALT Manufacturer=Taicom, ALT Manufacturers Part Number=TKH10MRLSM, Manufacturer=Molex, Supplier Part Number 1=WM7628CT-ND
J7: "CON PICOBLADE 14POS HEADER 1.25MM HORIZ SMD", ALT Manufacturer=Taicom, ALT Manufacturers Part Number=TKH14MRLSM, Manufacturer=Molex, Supplier Part Number 1=WM7631CT-ND
J8: "CON PICOBLADE 2POS HEADER 1.25MM VERT SMD", ALT Manufacturer=Taicom, ALT Manufacturers Part Number=TKH02MSLSM, Manufacturer=Molex, Manufacturers Part Number=533980271, Supplier Part Number 1=WM7606CT-ND
L1: library part "IND PWR 1.5UH 20% 1.7A 2.95MM x 2.95MM x 1.4MM", "IND PWR 1.5UH 20% 1.7A 2.95MM x 2.95MM x 1.4MM", Manufacturer=Coilcraft, Supplier Part Number 1=994-LPS3015-152MRC, Tolerance=20%
R1: library part "RES 0R 0201", "RES 0R 0201", Supplier Part Number 1=71-CRCW02010000Z0ED
R2 R6: library part "RES 4.7K 0201 1% 100PPM", "RES 4.7K 0201 1% 100PPM", Supplier Part Number 1=71-CRCW02014K70FKED, Tolerance=1%
R3: library part "RES 750R 0201 1% 100PPM", "RES 750R 0201 1% 100PPM", Supplier Part Number 1=71-CRCW0201750RFKED, Tolerance=1%
R4 R25 R27: library part "RES 330R 0201 1% 100PPM", "RES 330R 0201 1% 100PPM", Supplier Part Number 1=71-CRCW0201330RFKED, Tolerance=1%
R5: library part "RES 1.6K 0201 1% 100PPM", "RES 1.6K 0201 1% 100PPM", Supplier Part Number 1=71-CRCW02011K60FKED, Tolerance=1%
R7 R8 R15: library part "RES 0R 0402", "RES 0R 0402", Supplier Part Number 1=603-RC0402JR-070RL
R10 R18 R23 R24 R35: library part "RES 10K 0201 1% 100PPM", "RES 10K 0201 1% 100PPM", Supplier Part Number 1=71-CRCW020110K0FKED, Tolerance=1%
R11: library part "RES 3.3K 0201 1% 100PPM", "RES 3.3K 0201 1% 100PPM", Supplier Part Number 1=71-CRCW02013K30FKED, Tolerance=1%
R12: library part "RES 287K 0201 1% 100PPM", "RES 287K 0201 1% 100PPM", Supplier Part Number 1=71-CRCW0201287KFKED, Tolerance=1%
R13: library part "RES 51.1K 0201 1% 100PPM", "RES 51.1K 0201 1% 100PPM", Supplier Part Number 1=71-CRCW020151K1FKED, Tolerance=1%
R14: library part "RES 100K 0201 1% 100PPM", "RES 100K 0201 1% 100PPM", Supplier Part Number 1=71-CRCW0201100KFKED, Tolerance=1%
R16 R17: library part "RES 10K 0402 1% 100PPM", "RES 10K 0402 1% 100PPM", Supplier Part Number 1=71-CRCW0402-10K-E3, Tolerance=1%
R19 R22 R47: library part "RES 1M 0402 1% 100PPM", "RES 1M 0402 1% 100PPM", Supplier Part Number 1=71-CRCW0402-1.0M-E3, Tolerance=1%
R20: library part "RES 280K 0402 1% 100PPM", "RES 280K 0402 1% 100PPM", Supplier Part Number 1=603-RC0402FR-07280KL, Tolerance=1%
R21: library part "RES 100K 0402 1% 100PPM", "RES 100K 0402 1% 100PPM", Supplier Part Number 1=71-CRCW0402-100K-E3, Tolerance=1%
R26: library part "RES 620R 0201 1% 200PPM", "RES 620R 0201 1% 200PPM", Supplier Part Number 1=603-RC0201FR-07620RL, Tolerance=1%
R46: library part "RES 680K 0402 1% 100PPM", "RES 680K 0402 1% 100PPM", Supplier Part Number 1=603-RC0402FR-07680KL, Tolerance=1%
SW1 SW2: "SW SPST PB 50MA 12V SMT CK variant", Manufacturer=C&K, Manufacturers Part Number="PTS820J2xM SMTR LFS", Supplier Part Number 1=611-PTS820J25MSMTR
SW3: "SW REED SPST SMD", Manufacturer="Coto Technology", Manufacturers Part Number=CT05-1535-J1, Supplier Part Number 1=816-CT05-1535-J1
U1: "IC ISP Smart Bluetooth Module", Manufacturer=InsightSIP, Manufacturers Part Number=ISP1807-LR-ST, Temp Max=85, Temp Min=-40
U2: "IC GNSS NEO-M8N", Manufacturer=ublox, Temp Max=85, Temp Min=-40
U3: "IC MEM SERIAL NOR FLASH QSPI 128Mb/16MB 3.6V 166MHz WSON8 6X5", Manufacturer=ISSI, Supplier Part Number 1=2901145, Temp Max=105, Temp Min=-40
U4: "IC BATT CHG LI ION 4.2V (IP 4.3 - 6.5V) 500MA", Manufacturer="Texas Instruments", Manufacturers Part Number=BQ24230RGTR, Supplier Part Number 1=296-23937-1-ND, Temp Max=85, Temp Min=-40
U5: "IC VREG BUCK BOOST 500mA IP 1.8V-5.5V ADJ", Manufacturer="Texas Instruments", Supplier Part Number 1=296-34935-1-ND, Temp Max=85, Temp Min=-40
U6: "IC PULSE GENERATOR SOT23-6", Manufacturer="Analog Devices", Manufacturers Part Number=LTC6995IS6-1, Supplier Part Number 1=LTC6995IS6-1#TRMPBF, Temp Max=85, Temp Min=-40
U7: "IC LOGIC NAND 2-INPUT QUAD 14-DHVQFN", Manufacturer=Nexperia, Manufacturers Part Number=14-DHVQFN, Supplier Part Number 1=1727-8348-1-ND, Temp Max=125, Temp Min=-40
U8: "IC BATT MGMT 2.45V - 4.5V DSBGA-9", Manufacturer="Texas Instruments", Supplier Part Number 1=296-37460-1-ND, Temp Max=85, Temp Min=-40
U9: "IC IMU Accel/Gyro/magnet/temp SPI/I2C 12LGA", Manufacturer="Bosch Sensortec", Supplier Part Number 1=828-1087-1-ND, Temp Max=85, Temp Min=-40
U10: "IC SENSOR PRESSURE 0-14BAR SO8", Manufacturer="TE Connectivity", Manufacturers Part Number=MS580314BA01-00, Supplier Part Number 1=223-1626-5-ND, Temp Max=85, Temp Min=-40

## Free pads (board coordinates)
  round 0.5 on Top Overlay: ""(31.075,26.94)

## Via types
v1: diameter 0.4, hole 0.2, Top Layer to Bottom Layer, tented both sides, 631 vias
v2: diameter 0.23, hole 0.1, Top Layer to L2GND, tented top, 27 vias
v3: diameter 0.25, hole 0.125, L2GND to L3, 25 vias
v4: diameter 0.5, hole 0.2, Top Layer to Bottom Layer, 12 vias
v5: diameter 0.25, hole 0.125, L2GND to L3, tented both sides, 12 vias
v6: diameter 0.23, hole 0.1, Top Layer to L2GND, tented both sides, 12 vias
v7: diameter 0.23, hole 0.1, L5GND to Bottom Layer, tented both sides, 11 vias
v8: diameter 0.25, hole 0.125, L4 to L5GND, tented both sides, 11 vias
v9: diameter 0.3, hole 0.15, L3 to L4, tented both sides, 11 vias
v10: diameter 0.3, hole 0.15, L3 to L4, 11 vias
v11: diameter 0.4, hole 0.2, Top Layer to Bottom Layer, 5 vias
v12: diameter 1, hole 1, Top Layer to Bottom Layer, tented both sides, 1 vias

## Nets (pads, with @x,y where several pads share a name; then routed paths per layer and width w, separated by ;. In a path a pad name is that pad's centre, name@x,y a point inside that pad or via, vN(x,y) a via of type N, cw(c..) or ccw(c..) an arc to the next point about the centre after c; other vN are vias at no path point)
DCDC_3V3: C1.2 C2.1 C3.2 C4.2 C5.2 C6.2 C7.2 C8.2 C14.1 C35.2 C36.2 C42.2 D1.1 J3.1 J5.1 J7.1 J7.2 R2.2 R6.2 R10.2 R12.2 R23.2 R35.2 U5.D1 U9.1 U9.5 U9.8 U9.12 | length 32.5
  Top Layer w0.1: R10.2@49.675,10.65 R10.2@49.675,10.695
  Top Layer w0.2: C36.2@34.53,30.475 34.54,30.465 34.55,30.475 v1(34.925,30.475) U9.8@35.613,30.475 ; v1(35.75,27.625) R6.2@36.195,27.625 ; v1(35.925,28.475) 36.325,28.475 36.375,28.525 U9.12@36.375,28.713 ; U9.5@37.375,30.738 v1(37.375,31.45) C35.2@37.375,31.845 ; R2.2@38.055,27.61 38.065,27.6 v1(38.5,27.6) ; v1(38.125,28.575) 38.138,28.587 U9.1@38.138,28.975 ; C3.2@44.259,29.7 44.259,30.209 44.575,30.525 48.25,30.525 48.625,30.9 R35.2@48.625,31.62 ; J3.1@48.16,9.995 49.02,9.995 R10.2@49.675,10.65
  Top Layer w0.3: v1(4.275,23.525) J5.1@5.35,23.525 ; v1(5.4,24.225) 5.4,23.575 J5.1@5.375,23.55 J5.1@5.35,23.525 ; v1(6.45,23.525) J5.1@5.35,23.525 ; J7.2@26.025,29.625 26.05,29.6 v1(26.05,28.55) ; v1(26.05,30.7) 26.05,29.65 J7.2@26.125,29.575 ; J7.1@27.15,29.625 J7.1@27.275,29.625 ; v1(27.25,28.55) 27.25,29.6 J7.1@27.275,29.625 ; v1(27.3,30.7) 27.3,29.65 J7.1@27.275,29.625 ; v1(27.975,29.55) 27.35,29.55 J7.1@27.275,29.625 ; C6.2@31.05,4.25 31.075,4.275 v1(31.5,4.275) v1(31.9,4.275) C5.2@31.9,3.755 ; R12.2@42.559,27.205 43.35,27.205 C7.2@43.375,27.23 43.845,27.7 C1.2@44.259,27.7 ; C3.2@44.259,29.7 C4.2@44.259,28.7 C1.2@44.259,27.7 ; U5.D1@44.709,26.55 44.709,26.891 44.259,27.341 C1.2@44.259,27.7 ; C2.1@47.475,6.8 v1(47.475,7.3)
  Top Layer w0.4: C8.2@42.74,29.7 43.14,29.3 v1(43.5,29.3) ; v1(47.475,7.3) v1(47.475,7.7)
  Top Layer w1: J7.2@26.125,29.575 26.125,29.625 J7.1@27.15,29.625
  Bottom Layer w0.3: C42.2@12.825,1.225 v1(13.2,1.225) ; v1(31.8,14.55) C14.1@32.25,14.55 ; v1(33.375,6.225) 33.375,6.675 D1.1@34.225,7.525 ; v1(39.075,26.362) 39.087,26.375 R23.2@39.545,26.375
  other v1: 49.02,10 42.575,27.7 43.05,27.7 43.5,27.7 43.5,28.225 43.5,28.725 42.875,29.075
